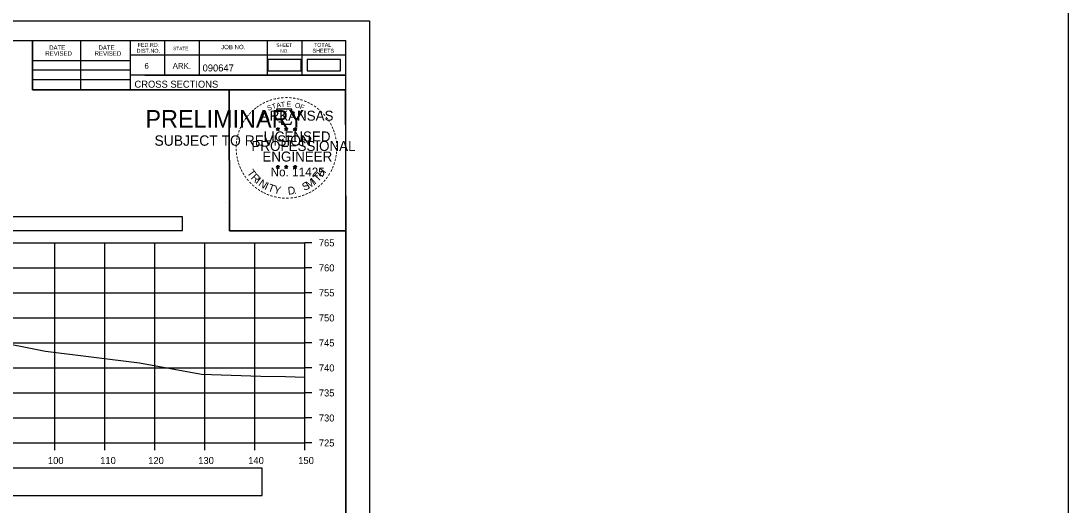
# Model space of a CAD drawing. Extents: x 1202951 to 1376887, y 378065 to 728038.
# Drawn here: x 1376677.9 to 1376887.3, y 378311.1 to 378407.8 of the extents above; entities that cross this region are included whole.
import ezdxf

# ---------------------------------------------------------------- set-up
doc = ezdxf.new("R2010")
doc.units = 0
for name, color, linetype in [('Default', 7, 'Continuous'), ('R_Alt Surface', 7, 'Continuous'), ('R_Axis', 7, 'Continuous'), ('R_Axis Annot', 7, 'Continuous'), ('R_Border', 7, 'Continuous'), ('R_Border PE', 7, 'Continuous'), ('R_Border Prem', 7, 'Continuous'), ('R_Exist Surface', 7, 'Continuous'), ('R_Grid', 7, 'Continuous'), ('R_No Plot', 7, 'Continuous')]:
    doc.layers.add(name, color=color, linetype=linetype)

msp = doc.modelspace()

# ---------------------------------------------------------------- linework, layer by layer
at = {"layer": 'Default'}
msp.add_lwpolyline([(1376735.11, 378397.84), (1376741.79, 378397.84), (1376741.79, 378400.15), (1376735.11, 378400.15)], close=True, dxfattribs=at)
at = {"layer": 'R_Alt Surface'}
for points in [[(1376727.24, 378397.84), (1376733.92, 378397.84), (1376733.92, 378400.15), (1376727.24, 378400.15)], [(1376434.67, 378365.98), (1376710.2, 378365.98), (1376710.2, 378368.68), (1376434.67, 378368.68)], [(1376615.43, 378312.96), (1376726.14, 378312.96), (1376726.14, 378318.48), (1376615.43, 378318.48)]]:
    msp.add_lwpolyline(points, close=True, dxfattribs=at)
at = {"layer": 'R_Axis'}
for p, q in [((1376734.67, 378323.48), (1376734.67, 378363.48)), ((1376736.07, 378363.48), (1376734.67, 378363.48)), ((1376736.07, 378358.48), (1376734.67, 378358.48)), ((1376736.07, 378353.48), (1376734.67, 378353.48)), ((1376736.07, 378348.48), (1376734.67, 378348.48)), ((1376736.07, 378343.48), (1376734.67, 378343.48)), ((1376736.07, 378338.48), (1376734.67, 378338.48)), ((1376736.07, 378333.48), (1376734.67, 378333.48)), ((1376736.07, 378328.48), (1376734.67, 378328.48)), ((1376434.67, 378323.48), (1376734.67, 378323.48)), ((1376684.67, 378322.08), (1376684.67, 378323.48)), ((1376694.67, 378322.08), (1376694.67, 378323.48)), ((1376704.67, 378322.08), (1376704.67, 378323.48)), ((1376714.67, 378322.08), (1376714.67, 378323.48)), ((1376724.67, 378322.08), (1376724.67, 378323.48)), ((1376734.67, 378322.08), (1376734.67, 378323.48)), ((1376736.07, 378323.48), (1376734.67, 378323.48))]:
    msp.add_line(p, q, dxfattribs=at)
at = {"layer": 'R_Border'}
for p, q in [((1376426.67, 378403.94), (1376742.85, 378403.94)), ((1376680.21, 378394.06), (1376680.21, 378403.94)), ((1376689.89, 378394.06), (1376689.89, 378403.94)), ((1376699.75, 378403.94), (1376699.75, 378394.06)), ((1376706.59, 378403.94), (1376706.59, 378397)), ((1376713.53, 378403.94), (1376713.53, 378397)), ((1376727.11, 378403.94), (1376727.11, 378397)), ((1376734.05, 378403.94), (1376734.05, 378397)), ((1376742.85, 378198.48), (1376742.85, 378403.94)), ((1376680.21, 378399.92), (1376699.75, 378399.92)), ((1376742.85, 378401), (1376699.75, 378401)), ((1376742.85, 378401.02), (1376742.85, 378401.02)), ((1376680.21, 378398.06), (1376699.75, 378398.06)), ((1376680.21, 378396.12), (1376699.75, 378396.12)), ((1376742.85, 378397), (1376699.75, 378397)), ((1376702.71, 378397), (1376742.85, 378397)), ((1376742.85, 378394.06), (1376680.21, 378394.06))]:
    msp.add_line(p, q, dxfattribs=at)
at = {"layer": 'R_Border PE'}
for p, q in [((1376728.94, 378386.31), (1376729.28, 378386.2)), ((1376728.94, 378386.31), (1376729.19, 378386.27)), ((1376728.94, 378386.31), (1376729.17, 378386.19)), ((1376729.07, 378385.91), (1376729.28, 378386.2)), ((1376729.07, 378385.91), (1376729.19, 378386.15)), ((1376729.07, 378385.91), (1376729.28, 378386.12)), ((1376729.28, 378386.57), (1376729.24, 378386.32)), ((1376729.28, 378386.2), (1376729.28, 378386.57)), ((1376729.28, 378386.57), (1376729.33, 378386.32)), ((1376729.63, 378386.31), (1376729.28, 378386.2)), ((1376729.5, 378385.91), (1376729.28, 378386.2)), ((1376729.5, 378385.91), (1376729.28, 378386.12)), ((1376729.63, 378386.31), (1376729.35, 378386.26)), ((1376729.5, 378385.91), (1376729.36, 378386.2)), ((1376729.63, 378386.31), (1376729.43, 378386.21)), ((1376730.61, 378386.31), (1376730.95, 378386.2)), ((1376730.61, 378386.31), (1376730.86, 378386.27)), ((1376730.61, 378386.31), (1376730.84, 378386.19)), ((1376730.74, 378385.91), (1376730.95, 378386.2)), ((1376730.74, 378385.91), (1376730.86, 378386.15)), ((1376730.74, 378385.91), (1376730.95, 378386.12)), ((1376730.95, 378386.57), (1376730.91, 378386.32)), ((1376730.95, 378386.2), (1376730.95, 378386.57)), ((1376730.95, 378386.57), (1376731, 378386.32)), ((1376731.3, 378386.31), (1376730.95, 378386.2)), ((1376731.17, 378385.91), (1376730.95, 378386.2)), ((1376731.17, 378385.91), (1376730.95, 378386.12)), ((1376731.3, 378386.31), (1376731.02, 378386.26)), ((1376731.17, 378385.91), (1376731.03, 378386.2)), ((1376731.3, 378386.31), (1376731.1, 378386.21)), ((1376732.37, 378386.3), (1376732.72, 378386.19)), ((1376732.37, 378386.3), (1376732.62, 378386.26)), ((1376732.37, 378386.3), (1376732.61, 378386.18)), ((1376732.5, 378385.89), (1376732.72, 378386.19)), ((1376732.5, 378385.89), (1376732.63, 378386.14)), ((1376732.5, 378385.89), (1376732.72, 378386.11)), ((1376732.72, 378386.56), (1376732.68, 378386.3)), ((1376732.72, 378386.19), (1376732.72, 378386.56)), ((1376732.72, 378386.56), (1376732.77, 378386.31)), ((1376733.07, 378386.3), (1376732.72, 378386.19)), ((1376732.93, 378385.89), (1376732.72, 378386.19)), ((1376732.93, 378385.89), (1376732.72, 378386.11)), ((1376733.07, 378386.3), (1376732.78, 378386.25)), ((1376732.93, 378385.89), (1376732.79, 378386.18)), ((1376733.07, 378386.3), (1376732.86, 378386.2)), ((1376729.28, 378378.99), (1376729.24, 378378.74)), ((1376729.28, 378378.63), (1376729.28, 378378.99)), ((1376729.28, 378378.99), (1376729.33, 378378.74)), ((1376730.95, 378378.99), (1376730.91, 378378.74)), ((1376730.95, 378378.63), (1376730.95, 378378.99)), ((1376730.95, 378378.99), (1376731, 378378.74)), ((1376732.72, 378378.98), (1376732.68, 378378.73)), ((1376732.72, 378378.62), (1376732.72, 378378.98)), ((1376732.72, 378378.98), (1376732.77, 378378.73)), ((1376728.93, 378378.74), (1376729.28, 378378.63)), ((1376728.93, 378378.74), (1376729.18, 378378.7)), ((1376728.93, 378378.74), (1376729.17, 378378.62)), ((1376729.06, 378378.33), (1376729.28, 378378.63)), ((1376729.06, 378378.33), (1376729.19, 378378.58)), ((1376729.06, 378378.33), (1376729.28, 378378.55)), ((1376729.63, 378378.74), (1376729.28, 378378.63)), ((1376729.49, 378378.33), (1376729.28, 378378.63)), ((1376729.49, 378378.33), (1376729.28, 378378.55)), ((1376729.63, 378378.74), (1376729.34, 378378.69)), ((1376729.49, 378378.33), (1376729.36, 378378.62)), ((1376729.63, 378378.74), (1376729.42, 378378.64)), ((1376730.6, 378378.74), (1376730.95, 378378.63)), ((1376730.6, 378378.74), (1376730.85, 378378.7)), ((1376730.6, 378378.74), (1376730.84, 378378.62)), ((1376730.73, 378378.33), (1376730.95, 378378.63)), ((1376730.73, 378378.33), (1376730.86, 378378.58)), ((1376730.73, 378378.33), (1376730.95, 378378.55)), ((1376731.3, 378378.74), (1376730.95, 378378.63)), ((1376731.16, 378378.33), (1376730.95, 378378.63)), ((1376731.16, 378378.33), (1376730.95, 378378.55)), ((1376731.3, 378378.74), (1376731.01, 378378.69)), ((1376731.16, 378378.33), (1376731.03, 378378.62)), ((1376731.3, 378378.74), (1376731.09, 378378.64)), ((1376732.37, 378378.73), (1376732.72, 378378.62)), ((1376732.37, 378378.73), (1376732.62, 378378.69)), ((1376732.37, 378378.73), (1376732.6, 378378.61)), ((1376732.5, 378378.32), (1376732.72, 378378.62)), ((1376732.5, 378378.32), (1376732.63, 378378.57)), ((1376732.5, 378378.32), (1376732.71, 378378.54)), ((1376732.93, 378378.32), (1376732.71, 378378.54)), ((1376733.06, 378378.73), (1376732.72, 378378.62)), ((1376732.93, 378378.32), (1376732.72, 378378.62)), ((1376733.06, 378378.73), (1376732.78, 378378.68)), ((1376732.93, 378378.32), (1376732.79, 378378.61)), ((1376733.06, 378378.73), (1376732.86, 378378.63))]:
    msp.add_line(p, q, dxfattribs=at)
for points in [[(1376728.98, 378390.19), (1376729.25, 378389.36)], [(1376732.49, 378389.27), (1376732.63, 378389.55), (1376731.94, 378389.53), (1376732.09, 378390.19), (1376728.98, 378390.19)], [(1376729.47, 378387.77), (1376729.47, 378387.68), (1376730.03, 378387.66), (1376729.98, 378387.19), (1376731.85, 378387.19), (1376732.05, 378387.73)], [(1376729.28, 378386.57), (1376729.5, 378385.91), (1376728.94, 378386.31), (1376729.63, 378386.31), (1376729.07, 378385.91), (1376729.28, 378386.57)], [(1376730.95, 378386.57), (1376731.17, 378385.91), (1376730.61, 378386.31), (1376731.3, 378386.31), (1376730.74, 378385.91), (1376730.95, 378386.57)], [(1376732.72, 378386.56), (1376732.93, 378385.89), (1376732.37, 378386.3), (1376733.07, 378386.3), (1376732.5, 378385.89), (1376732.72, 378386.56)], [(1376729.28, 378378.99), (1376729.49, 378378.33), (1376728.93, 378378.74), (1376729.63, 378378.74), (1376729.06, 378378.33), (1376729.28, 378378.99)], [(1376730.95, 378378.99), (1376731.16, 378378.33), (1376730.6, 378378.74), (1376731.3, 378378.74), (1376730.73, 378378.33), (1376730.95, 378378.99)], [(1376732.72, 378378.98), (1376732.93, 378378.32), (1376732.37, 378378.73), (1376733.06, 378378.73), (1376732.5, 378378.32), (1376732.72, 378378.98)]]:
    msp.add_lwpolyline(points, dxfattribs=at)
for centre, radius in [((1376729.28, 378386.2), 0.172), ((1376729.28, 378386.2), 0.145), ((1376729.28, 378386.2), 0.116), ((1376729.28, 378386.2), 0.0991), ((1376729.28, 378386.2), 0.0747), ((1376729.28, 378386.2), 0.0495), ((1376729.28, 378386.2), 0.0296), ((1376730.95, 378386.2), 0.172), ((1376730.95, 378386.2), 0.145), ((1376730.95, 378386.2), 0.116), ((1376730.95, 378386.2), 0.0991), ((1376730.95, 378386.2), 0.0747), ((1376730.95, 378386.2), 0.0495), ((1376730.95, 378386.2), 0.0296), ((1376732.72, 378386.19), 0.172), ((1376732.72, 378386.19), 0.145), ((1376732.72, 378386.19), 0.116), ((1376732.72, 378386.19), 0.0991), ((1376732.72, 378386.19), 0.0747), ((1376732.72, 378386.19), 0.0495), ((1376732.72, 378386.19), 0.0296), ((1376729.28, 378378.63), 0.172), ((1376729.28, 378378.63), 0.145), ((1376729.28, 378378.63), 0.116), ((1376729.28, 378378.63), 0.0991), ((1376729.28, 378378.63), 0.0747), ((1376729.28, 378378.63), 0.0495), ((1376729.28, 378378.63), 0.0296), ((1376730.95, 378378.63), 0.172), ((1376730.95, 378378.63), 0.145), ((1376730.95, 378378.63), 0.116), ((1376730.95, 378378.63), 0.0991), ((1376730.95, 378378.63), 0.0747), ((1376730.95, 378378.63), 0.0495), ((1376730.95, 378378.63), 0.0296), ((1376732.72, 378378.62), 0.172), ((1376732.72, 378378.62), 0.145), ((1376732.72, 378378.62), 0.116), ((1376732.72, 378378.62), 0.0991), ((1376732.72, 378378.62), 0.0747), ((1376732.72, 378378.62), 0.0495), ((1376732.72, 378378.62), 0.0296)]:
    msp.add_circle(centre, radius, dxfattribs=at)
at = {"layer": 'R_Exist Surface'}
msp.add_lwpolyline([(1376671.66, 378344.06), (1376682.81, 378341.81), (1376701.63, 378339.48), (1376714.04, 378337.25), (1376725.88, 378336.83), (1376730.78, 378336.75), (1376734.67, 378336.61)], dxfattribs=at)
at = {"layer": 'R_Grid'}
for p, q in [((1376434.67, 378363.48), (1376734.67, 378363.48)), ((1376684.67, 378323.48), (1376684.67, 378363.48)), ((1376694.67, 378323.48), (1376694.67, 378363.48)), ((1376704.67, 378323.48), (1376704.67, 378363.48)), ((1376714.67, 378323.48), (1376714.67, 378363.48)), ((1376724.67, 378323.48), (1376724.67, 378363.48)), ((1376734.67, 378323.48), (1376734.67, 378363.48)), ((1376434.67, 378358.48), (1376734.67, 378358.48)), ((1376434.67, 378353.48), (1376734.67, 378353.48)), ((1376434.67, 378348.48), (1376734.67, 378348.48)), ((1376434.67, 378343.48), (1376734.67, 378343.48)), ((1376434.67, 378338.48), (1376734.67, 378338.48)), ((1376434.67, 378333.48), (1376734.67, 378333.48)), ((1376434.67, 378328.48), (1376734.67, 378328.48)), ((1376434.67, 378323.48), (1376734.67, 378323.48))]:
    msp.add_line(p, q, dxfattribs=at)
at = {"layer": 'R_No Plot'}
for p, q in [((1376414.27, 378407.83), (1376747.6, 378407.83)), ((1376718.89, 378371.6), (1376718.89, 378371.6))]:
    msp.add_line(p, q, dxfattribs=at)
for points in [[(1376303.24, 380162.87), (1376887.29, 380162.87), (1376887.29, 378065.39), (1376303.24, 378065.39)], [(1376414.26, 378407.83), (1376747.6, 378407.83), (1376747.6, 378194.5), (1376414.26, 378194.5)], [(1376660.59, 378403.94), (1376680.21, 378403.94), (1376680.21, 378394.06), (1376696.32, 378394.06), (1376719.52, 378394.06), (1376719.64, 378365.9), (1376742.85, 378365.9), (1376742.85, 378198.48), (1376426.67, 378198.48), (1376426.67, 378403.94)], [(1376719.52, 378394.06), (1376742.73, 378394.06), (1376742.85, 378365.9), (1376719.64, 378365.9)]]:
    msp.add_lwpolyline(points, close=True, dxfattribs=at)

# ---------------------------------------------------------------- texts
at = {"layer": 'R_Axis Annot'}
for s, p in [('765', (1376737.47, 378362.78)), ('760', (1376737.47, 378357.78)), ('755', (1376737.47, 378352.78)), ('750', (1376737.47, 378347.78)), ('745', (1376737.47, 378342.78)), ('740', (1376737.47, 378337.78)), ('735', (1376737.47, 378332.78)), ('730', (1376737.47, 378327.78)), ('725', (1376737.47, 378322.78)), ('100', (1376683.3, 378319.28)), ('110', (1376693.75, 378319.28)), ('120', (1376703.35, 378319.28)), ('130', (1376713.35, 378319.28)), ('140', (1376723.35, 378319.28)), ('150', (1376733.35, 378319.28))]:
    msp.add_text(s, height=1.4, dxfattribs=at).set_placement(p)
at = {"layer": 'R_Border'}
for s, height, p in [('DATE', 0.879, (1376683.55, 378402.07)), ('DATE', 0.879, (1376693.41, 378402.07)), ('DIST.NO.', 0.782, (1376701.03, 378401.48)), ('FED.RD.', 0.782, (1376701.23, 378402.66)), ('STATE', 0.684, (1376708.35, 378401.98)), ('JOB NO.', 0.879, (1376717.93, 378402.18)), ('SHEET', 0.684, (1376728.97, 378402.66)), ('NO.', 0.684, (1376729.75, 378401.48)), ('SHEETS', 0.782, (1376736.21, 378401.48)), ('TOTAL', 0.782, (1376736.49, 378402.66)), ('REVISED', 0.879, (1376682.77, 378400.89)), ('REVISED', 0.879, (1376692.63, 378400.89)), ('6', 1.17, (1376702.59, 378398.26)), ('ARK.', 1.172, (1376708.25, 378398.26)), ('090647', 1.4, (1376714.23, 378397.74)), ('CROSS SECTIONS', 1.4, (1376700.61, 378394.49))]:
    msp.add_text(s, height=height, rotation=360, dxfattribs=at).set_placement(p)
at = {"layer": 'R_Border PE'}
for s, height, rotation, p in [('-', 1.6, 28.7918, (1376726.46, 378390.73)), ('-', 1.6, 24.3072, (1376727.09, 378391.05)), ('-', 1.6, 19.1761, (1376727.72, 378391.32)), ('T', 1, 16.4036, (1376728.25, 378390.2)), ('-', 1.6, 13.6301, (1376728.47, 378391.56)), ('A', 1, 11.2132, (1376729.07, 378390.45)), ('-', 1.6, 10.2193, (1376729.15, 378391.72)), ('T', 1, 6.0228, (1376729.92, 378390.62)), ('-', 1.6, 5.8968, (1376729.88, 378391.83)), ('-', 1.6, 0.1862, (1376730.65, 378391.9)), ('E', 1, 0.8323, (1376731.03, 378390.73)), ('-', 1.6, 357.743, (1376731.38, 378391.89)), ('-', 1.6, 352.1617, (1376732.12, 378391.83)), ('O', 1, 350.4515, (1376732.63, 378390.52)), ('-', 1.6, 347.2049, (1376732.84, 378391.72)), ('-', 1.6, 342.3362, (1376733.47, 378391.57)), ('-', 1.6, 337.8551, (1376734.21, 378391.34)), ('-', 1.6, 334.1211, (1376734.84, 378391.07)), ('-', 1.6, 48.423, (1376723.93, 378388.69)), ('-', 1.6, 42.9622, (1376724.37, 378389.17)), ('-', 1.6, 38.9507, (1376724.81, 378389.59)), ('-', 1.6, 36.2317, (1376725.28, 378389.97)), ('-', 1.6, 34.0636, (1376725.86, 378390.36)), ('ARKANSAS', 2, 360, (1376725.83, 378387.9)), ('S', 1, 21.594, (1376727.33, 378389.87)), ('F', 1, 340.0707, (1376733.58, 378390.29)), ('-', 1.6, 329.6409, (1376735.42, 378390.79)), ('-', 1.6, 325.8627, (1376736.06, 378390.43)), ('-', 1.6, 320.5297, (1376736.67, 378390)), ('-', 1.6, 315.5786, (1376737.27, 378389.51)), ('-', 1.6, 309.8797, (1376737.84, 378388.96)), ('-', 1.6, 62.8713, (1376722.47, 378386.5)), ('-', 1.6, 58.0706, (1376722.78, 378387.11)), ('-', 1.6, 54.2325, (1376723.11, 378387.64)), ('-', 1.6, 50.6142, (1376723.52, 378388.21)), ('-', 1.6, 306.6522, (1376738.37, 378388.36)), ('-', 1.4, 303.6753, (1376738.85, 378387.79)), ('-', 1.6, 299.6684, (1376739.17, 378387.19)), ('-', 1.6, 75.461, (1376721.8, 378384.55)), ('-', 1.6, 72.3945, (1376721.99, 378385.26)), ('-', 1.6, 67.7743, (1376722.21, 378385.89)), ('LICENSED', 2, 360, (1376726.43, 378383.75)), ('DWB', 0.01, 360, (1376729.27, 378386.2)), ('DWB', 0.01, 360, (1376730.94, 378386.2)), ('DWB', 0.01, 360, (1376732.71, 378386.19)), ('-', 1.6, 294.6628, (1376739.49, 378386.57)), ('-', 1.6, 290.5728, (1376739.75, 378386)), ('-', 1.6, 285.1233, (1376739.99, 378385.42)), ('-', 1.6, 89.0622, (1376721.56, 378382.44)), ('-', 1.6, 85.1863, (1376721.59, 378383.14)), ('-', 1.6, 81.2013, (1376721.66, 378383.83)), ('PROFESSIONAL', 2, 360, (1376724, 378381.85)), ('-', 1.6, 280.5493, (1376740.19, 378384.68)), ('-', 1.6, 276.5962, (1376740.35, 378383.91)), ('-', 1.6, 274.3301, (1376740.41, 378383.19)), ('-', 1.6, 94.1959, (1376721.6, 378381.72)), ('-', 1.6, 98.9479, (1376721.67, 378381.05)), ('ENGINEER', 2, 360, (1376726.19, 378379.73)), ('-', 1.6, 260.9953, (1376740.35, 378381.23)), ('-', 1.6, 263.5172, (1376740.42, 378381.89)), ('-', 1.6, 269.9407, (1376740.44, 378382.55)), ('-', 1.6, 101.7149, (1376721.81, 378380.32)), ('-', 1.6, 105.4578, (1376721.97, 378379.72)), ('-', 1.6, 109.0874, (1376722.18, 378379.09)), ('-', 1.6, 114.0643, (1376722.44, 378378.49)), ('-', 1.6, 247.8887, (1376739.84, 378379.16)), ('-', 1.6, 252.8681, (1376740.06, 378379.84)), ('-', 1.6, 255.7626, (1376740.24, 378380.56)), ('-', 1.6, 115.7289, (1376722.74, 378377.88)), ('-', 1.6, 120.4471, (1376723.1, 378377.29)), ('-', 1.6, 125.8934, (1376723.5, 378376.73)), ('T', 1.54, 306.0406, (1376723.04, 378377.47)), ('R', 1.54, 314.005, (1376723.8, 378376.42)), ('No. 11425', 1.757, 360, (1376727.82, 378376.77)), ('DWB', 0.01, 360, (1376729.27, 378378.62)), ('DWB', 0.01, 360, (1376730.94, 378378.63)), ('DWB', 0.01, 360, (1376732.7, 378378.62)), ('T', 1.54, 46.6444, (1376737.27, 378375.56)), ('H', 1.54, 54.6088, (1376738.16, 378376.5)), ('-', 1.6, 233.8452, (1376738.78, 378377.13)), ('-', 1.6, 239.0712, (1376739.18, 378377.78)), ('-', 1.6, 244.6197, (1376739.58, 378378.53)), ('-', 1.6, 130.7181, (1376723.96, 378376.18)), ('-', 1.6, 134.2238, (1376724.48, 378375.63)), ('-', 1.6, 138.9338, (1376725.01, 378375.17)), ('-', 1.6, 144.6463, (1376725.56, 378374.76)), ('I', 1.54, 321.9694, (1376724.7, 378375.49)), ('N', 1.54, 326.5002, (1376725.27, 378375.02)), ('I', 1.54, 335.3603, (1376726.48, 378374.23)), ('T', 1.54, 339.8912, (1376727.14, 378373.9)), ('Y', 1.54, 347.8556, (1376728.36, 378373.46)), ('D', 1.54, 6.3969, (1376731.34, 378373.1)), ('S', 1.54, 26.9312, (1376734.59, 378373.83)), ('M', 1.54, 32.6563, (1376735.43, 378374.24)), ('I', 1.54, 42.1136, (1376736.71, 378375.08)), ('-', 1.6, 221.0851, (1376737.35, 378375.49)), ('-', 1.6, 225.7653, (1376737.87, 378376)), ('-', 1.6, 231.2538, (1376738.35, 378376.56)), ('-', 1.6, 148.0898, (1376726.12, 378374.39)), ('-', 1.6, 151.5704, (1376726.7, 378374.07)), ('-', 1.6, 154.6002, (1376727.22, 378373.82)), ('-', 1.6, 158.5612, (1376727.85, 378373.56)), ('-', 1.6, 162.7983, (1376728.53, 378373.35)), ('-', 1.6, 167.5555, (1376729.25, 378373.19)), ('-', 1.6, 173.1155, (1376730.02, 378373.08)), ('-', 1.6, 176.5183, (1376730.77, 378373.02)), ('-', 1.6, 185.8167, (1376732.32, 378373.12)), ('-', 1.6, 191.2858, (1376733.06, 378373.25)), ('.', 1.54, 13.7642, (1376732.53, 378373.23)), ('-', 1.6, 195.4743, (1376733.79, 378373.45)), ('-', 1.6, 200.7184, (1376734.46, 378373.69)), ('-', 1.6, 204.2516, (1376735.08, 378373.97)), ('-', 1.6, 207.3568, (1376735.71, 378374.28)), ('-', 1.6, 212.2491, (1376736.27, 378374.63)), ('-', 1.6, 215.7363, (1376736.8, 378375.02)), ('-', 1.6, 181.5918, (1376731.51, 378373.04))]:
    msp.add_text(s, height=height, rotation=rotation, dxfattribs=at).set_placement(p)
at = {"layer": 'R_Border Prem'}
for s, height, p in [('PRELIMINARY', 3.5, (1376702.8, 378386.52)), ('DWB', 0.01, (1376703.55, 378388.37)), ('SUBJECT TO REVISION', 2.0751, (1376704.61, 378382.89))]:
    msp.add_text(s, height=height, rotation=360, dxfattribs=at).set_placement(p)

doc.saveas('drawing.dxf')
